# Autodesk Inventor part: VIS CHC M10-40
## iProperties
Created: 2004-11
Part Number: VIS CHC M10-40
Document SubType Name: Modeling
Designer: Bruno
Manufacturer: Standard
Standards Organization: Custom
Author: Bruno
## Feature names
1. Base1
